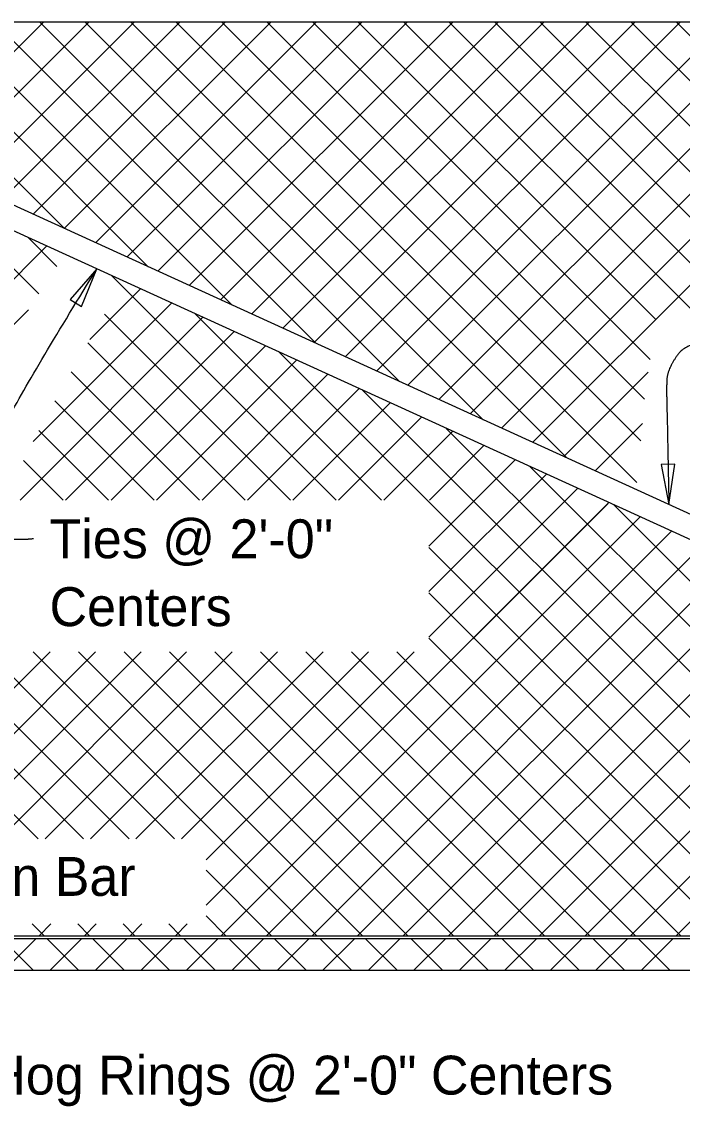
# Model space of a CAD drawing. Extents: x 0 to 41, y -96 to 25.
# Drawn here: x 7.46 to 10.89, y 14.93 to 20.56 of the extents above; entities that cross this region are included whole.
import ezdxf

# ---------------------------------------------------------------- set-up
doc = ezdxf.new("R2010")
doc.units = 0
for name, color, linetype in [('Dimension', 7, 'Continuous'), ('Miscellaneous', 7, 'Continuous'), ('SteelMisc', 7, 'Continuous'), ('SupstrConc', 7, 'Continuous'), ('TextStructures', 7, 'Continuous')]:
    doc.layers.add(name, color=color, linetype=linetype)

msp = doc.modelspace()

# ---------------------------------------------------------------- linework, layer by layer
at = {"layer": 'Dimension'}
for points in [[(7.8529, 19.2743), (7.7139, 19.1153), (7.774, 19.0784)], [(10.817, 18.0525), (10.8482, 18.2614), (10.7777, 18.26)]]:
    msp.add_lwpolyline(points, close=True, dxfattribs=at)
for points in [[(7.5254, 17.8747), (7.3945, 17.8605), (7.2116, 17.9278), (7.2201, 18.2544), (7.853, 19.2743)], [(11.1949, 18.9047), (10.9254, 18.9129), (10.8073, 18.7544), (10.8043, 18.6333), (10.809, 18.4655), (10.817, 18.0525)]]:
    msp.add_open_spline(points, degree=2, dxfattribs=at)
at = {"layer": 'Miscellaneous'}
for p, q in [((6.6129, 20.5552), (7.6858, 19.4824)), ((6.8486, 20.5552), (8.1195, 19.2843)), ((6.8749, 19.8526), (7.5775, 20.5552)), ((7.0367, 19.7787), (7.8132, 20.5552)), ((7.0843, 20.5552), (8.5533, 19.0862)), ((7.1985, 19.7048), (8.0489, 20.5552)), ((7.32, 20.5552), (8.9871, 18.8881)), ((7.3603, 19.631), (8.2846, 20.5552)), ((7.5222, 19.5571), (8.5203, 20.5552)), ((7.5557, 20.5552), (9.4209, 18.69)), ((7.684, 19.4832), (8.756, 20.5552)), ((7.7914, 20.5552), (9.8547, 18.4919)), ((7.8458, 19.4093), (8.9917, 20.5552)), ((8.0076, 19.3354), (9.2274, 20.5552)), ((8.0271, 20.5552), (10.2885, 18.2938)), ((8.1694, 19.2615), (9.4631, 20.5552)), ((8.2628, 20.5552), (10.6511, 18.1669)), ((8.3312, 19.1876), (9.6988, 20.5552)), ((8.493, 19.1137), (9.9345, 20.5552)), ((8.4985, 20.5552), (10.6713, 18.3824)), ((8.6548, 19.0398), (10.1702, 20.5552)), ((8.7342, 20.5552), (10.6914, 18.598)), ((8.8166, 18.9659), (10.4059, 20.5552)), ((8.9699, 20.5552), (10.7204, 18.8047)), ((8.9785, 18.892), (10.6416, 20.5552)), ((9.1403, 18.8182), (10.8773, 20.5552)), ((9.2056, 20.5552), (10.7486, 19.0123)), ((9.3021, 18.7443), (11.113, 20.5552)), ((9.4413, 20.5552), (10.9489, 19.0476)), ((9.4639, 18.6704), (11.3487, 20.5552)), ((9.6257, 18.5965), (11.5844, 20.5552)), ((9.677, 20.5552), (11.1846, 19.0476)), ((9.7875, 18.5226), (11.8201, 20.5552)), ((9.9127, 20.5552), (11.4203, 19.0476)), ((9.9493, 18.4487), (12.0558, 20.5552)), ((10.1111, 18.3748), (12.2915, 20.5552)), ((10.1484, 20.5552), (11.656, 19.0476)), ((10.3841, 20.5552), (11.8917, 19.0476)), ((10.6198, 20.5552), (12.1274, 19.0476)), ((10.8555, 20.5552), (12.3631, 19.0476)), ((7.0608, 19.6359), (7.552, 19.1447)), ((7.4946, 19.4378), (7.6462, 19.2862)), ((5.5946, 17.3938), (7.5935, 19.3927)), ((7.9284, 19.2398), (9.0923, 18.0758)), ((7.8165, 18.9086), (8.0789, 19.171)), ((5.5946, 17.1581), (7.498, 19.0615)), ((7.5224, 18.3788), (8.2407, 19.0971)), ((7.4551, 18.0758), (8.4025, 19.0232)), ((7.8927, 19.0397), (8.8566, 18.0758)), ((8.3621, 19.0417), (9.0053, 18.3985)), ((5.5946, 18.9808), (7.5666, 17.0088)), ((7.6908, 18.0758), (8.5643, 18.9493)), ((7.8061, 18.8906), (8.6209, 18.0758)), ((7.9265, 18.0758), (8.7262, 18.8755)), ((8.7959, 18.8436), (11.8219, 15.8177)), ((8.1622, 18.0758), (8.888, 18.8016)), ((5.5946, 18.7451), (8.0202, 16.3195)), ((7.7203, 18.7407), (8.3852, 18.0758)), ((8.3979, 18.0758), (9.0498, 18.7277)), ((10.273, 18.3009), (10.7102, 18.7382)), ((8.6336, 18.0758), (9.2116, 18.6538)), ((9.2297, 18.6455), (12.0576, 15.8177)), ((7.6356, 18.5897), (8.1495, 18.0758)), ((8.8693, 18.0758), (9.3734, 18.5799)), ((5.5946, 18.5094), (7.7845, 16.3195)), ((9.105, 18.0758), (9.5352, 18.506)), ((9.6635, 18.4474), (12.2933, 15.8177)), ((10.4348, 18.227), (10.6796, 18.4719)), ((7.5528, 18.4368), (7.9138, 18.0758)), ((8.9756, 18.4282), (9.328, 18.0758)), ((9.3407, 18.0758), (9.697, 18.4321)), ((9.5764, 18.0758), (9.8589, 18.3582)), ((5.5963, 18.272), (7.5488, 16.3195)), ((7.4733, 18.2806), (7.6781, 18.0758)), ((9.5734, 17.837), (10.0207, 18.2843)), ((10.0973, 18.2494), (12.529, 15.8177)), ((9.5734, 17.6013), (10.1825, 18.2105)), ((9.5734, 17.3656), (10.3443, 18.1366)), ((8.419, 15.9756), (10.5061, 18.0627)), ((9.8004, 17.357), (10.5004, 18.0569)), ((10.531, 18.0513), (12.7647, 15.8177)), ((8.4968, 15.8177), (10.6679, 17.9888)), ((8.7325, 15.8177), (10.8297, 17.9149)), ((8.9682, 15.8177), (10.9915, 17.841)), ((9.5734, 17.8305), (11.5862, 15.8177)), ((9.2039, 15.8177), (11.1534, 17.7671)), ((9.4396, 15.8177), (11.3152, 17.6932)), ((9.6753, 15.8177), (11.477, 17.6193)), ((9.5734, 17.5948), (11.3505, 15.8177)), ((9.911, 15.8177), (11.6388, 17.5454)), ((10.1467, 15.8177), (11.8006, 17.4716)), ((10.3824, 15.8177), (11.9624, 17.3977)), ((9.5734, 17.3591), (11.1147, 15.8177)), ((10.6181, 15.8177), (12.1242, 17.3238)), ((6.6416, 16.3195), (7.6109, 17.2888)), ((6.8773, 16.3195), (7.8466, 17.2888)), ((7.113, 16.3195), (8.0823, 17.2888)), ((7.3487, 16.3195), (8.318, 17.2888)), ((7.5223, 17.2888), (8.9934, 15.8177)), ((7.5844, 16.3195), (8.5537, 17.2888)), ((7.758, 17.2888), (9.2291, 15.8177)), ((7.8201, 16.3195), (8.7894, 17.2888)), ((7.9937, 17.2888), (9.4648, 15.8177)), ((8.0558, 16.3195), (9.0251, 17.2888)), ((8.2294, 17.2888), (9.7005, 15.8177)), ((8.2915, 16.3195), (9.2608, 17.2888)), ((8.419, 16.2113), (9.4965, 17.2888)), ((8.4651, 17.2888), (9.9362, 15.8177)), ((8.7008, 17.2888), (10.1719, 15.8177)), ((8.9365, 17.2888), (10.4076, 15.8177)), ((9.1722, 17.2888), (10.6433, 15.8177)), ((9.4079, 17.2888), (10.879, 15.8177)), ((10.8538, 15.8177), (12.286, 17.2499)), ((7.5663, 17.0091), (8.2559, 16.3195)), ((8.419, 16.1564), (8.7577, 15.8177)), ((8.419, 15.9207), (8.522, 15.8177)), ((7.5186, 15.8783), (7.5792, 15.8177)), ((7.554, 15.8177), (7.6146, 15.8783)), ((7.7543, 15.8783), (7.8149, 15.8177)), ((7.7897, 15.8177), (7.8503, 15.8783)), ((7.99, 15.8783), (8.0506, 15.8177)), ((8.0254, 15.8177), (8.086, 15.8783)), ((8.2257, 15.8783), (8.2863, 15.8177)), ((8.2611, 15.8177), (8.3217, 15.8783)), ((7.3583, 15.8029), (7.5227, 15.6384)), ((7.3748, 15.6384), (7.5392, 15.8029)), ((7.594, 15.8029), (7.7584, 15.6384)), ((7.6105, 15.6384), (7.7749, 15.8029)), ((7.8297, 15.8029), (7.9941, 15.6384)), ((7.8462, 15.6384), (8.0106, 15.8029)), ((8.0654, 15.8029), (8.2298, 15.6384)), ((8.0819, 15.6384), (8.2463, 15.8029)), ((8.3011, 15.8029), (8.4656, 15.6384)), ((8.3176, 15.6384), (8.482, 15.8029)), ((8.5368, 15.8029), (8.7013, 15.6384)), ((8.5533, 15.6384), (8.7177, 15.8029)), ((8.7725, 15.8029), (8.937, 15.6384)), ((8.789, 15.6384), (8.9534, 15.8029)), ((9.0082, 15.8029), (9.1727, 15.6384)), ((9.0247, 15.6384), (9.1892, 15.8029)), ((9.2439, 15.8029), (9.4084, 15.6384)), ((9.2604, 15.6384), (9.4249, 15.8029)), ((9.4796, 15.8029), (9.6441, 15.6384)), ((9.4961, 15.6384), (9.6606, 15.8029)), ((9.7153, 15.8029), (9.8798, 15.6384)), ((9.7318, 15.6384), (9.8963, 15.8029)), ((9.951, 15.8029), (10.1155, 15.6384)), ((9.9675, 15.6384), (10.132, 15.8029)), ((10.1867, 15.8029), (10.3512, 15.6384)), ((10.2032, 15.6384), (10.3677, 15.8029)), ((10.4224, 15.8029), (10.5869, 15.6384)), ((10.4389, 15.6384), (10.6034, 15.8029)), ((10.6581, 15.8029), (10.8226, 15.6384)), ((10.6746, 15.6384), (10.8391, 15.8029))]:
    msp.add_line(p, q, dxfattribs=at)
at = {"layer": 'SteelMisc'}
for p, q in [((5.6317, 20.5552), (15.0294, 20.5552)), ((14.9671, 16.1573), (5.7264, 20.3771)), ((14.9174, 16.0483), (5.6703, 20.2709)), ((5.6317, 15.8029), (15.0294, 15.8029)), ((5.633, 15.8177), (15.0028, 15.8177))]:
    msp.add_line(p, q, dxfattribs=at)
at = {"layer": 'SupstrConc'}
msp.add_line((5.4696, 15.6384), (11.9379, 15.6384), dxfattribs=at)

# ---------------------------------------------------------------- texts
at = {"layer": 'Dimension'}
for s, p in [('Ties @ 2\'-0" ', (7.6078, 17.7742)), ('Centers', (7.6078, 17.4222))]:
    msp.add_text(s, height=0.2016, dxfattribs=at).set_placement(p)
at = {"layer": 'TextStructures'}
for s, p in [('Tension Bar', (6.6007, 16.0239)), ('Hog Rings @ 2\'-0" Centers', (7.2903, 14.994))]:
    msp.add_text(s, height=0.2016, dxfattribs=at).set_placement(p)

doc.saveas('drawing.dxf')
